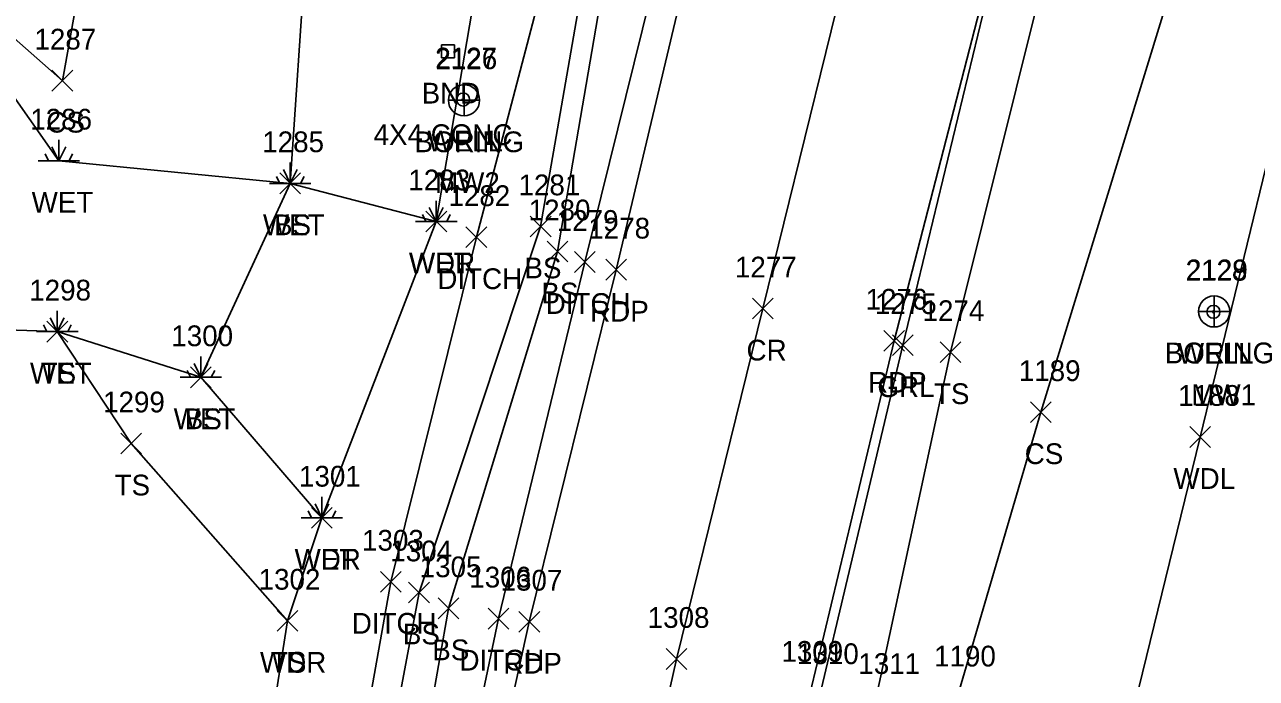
# Model space of a CAD drawing. Extents: x 1551995 to 1555700, y 777276 to 783130.
# Drawn here: x 1554843.1 to 1554961.7, y 777956 to 778019 of the extents above; entities that cross this region are included whole.
import ezdxf

# ---------------------------------------------------------------- set-up
doc = ezdxf.new("R2010")
doc.units = 0
for name, color, linetype in [('D_A', 7, 'Continuous'), ('D_I', 7, 'Continuous'), ('D_TIC', 7, 'Continuous'), ('DD', 7, 'Continuous'), ('G_A', 7, 'Continuous'), ('G_I', 7, 'Continuous'), ('GA_P', 7, 'Continuous'), ('L_A', 7, 'Continuous'), ('L_I', 7, 'Continuous'), ('L_TIC', 7, 'Continuous'), ('LAWA', 7, 'Continuous'), ('LELB', 7, 'Continuous'), ('Level 18', 7, 'Continuous'), ('LWET', 7, 'Continuous'), ('M_A', 7, 'Continuous'), ('M_C', 7, 'Continuous'), ('P_A', 7, 'Continuous'), ('P_I', 7, 'Continuous'), ('P_TIC', 7, 'Continuous'), ('PET', 7, 'Continuous'), ('PRC', 7, 'Continuous'), ('R_A', 7, 'Continuous'), ('R_I', 7, 'Continuous'), ('R_TIC', 7, 'Continuous'), ('RGR', 7, 'Continuous'), ('U_A', 7, 'Continuous'), ('U_C', 7, 'Continuous'), ('U_I', 7, 'Continuous'), ('UWW', 7, 'Continuous')]:
    doc.layers.add(name, color=color, linetype=linetype)

msp = doc.modelspace()

# ---------------------------------------------------------------- linework, layer by layer
at = {"layer": 'D_TIC'}
for points in [[(1554885.57, 777997.5), (1554887.57, 777999.5)], [(1554887.57, 777997.5), (1554885.57, 777999.5)], [(1554896.01, 777995.11), (1554898.01, 777997.11)], [(1554898.01, 777995.11), (1554896.01, 777997.11)], [(1554877.33, 777964.3), (1554879.33, 777966.3)], [(1554879.33, 777964.3), (1554877.33, 777966.3)], [(1554887.71, 777960.75), (1554889.71, 777962.75)], [(1554889.71, 777960.75), (1554887.71, 777962.75)]]:
    msp.add_lwpolyline(points, dxfattribs=at)
at = {"layer": 'DD'}
for points in [[(1554922.06, 778109.96), (1554923.19, 778109.15), (1554925.69, 778108.05), (1554928.67, 778106.77), (1554922.03, 778089.94), (1554922.01, 778087.44), (1554918.96, 778075.67), (1554907.32, 778037.79), (1554897.01, 777996.11), (1554888.71, 777961.75), (1554879.52, 777917.82), (1554870.92, 777875.83), (1554859.53, 777827.03), (1554848.28, 777775.3), (1554842.42, 777742.65), (1554832.08, 777696.16), (1554826.68, 777674.46), (1554825.9, 777662.94)], [(1554922.06, 778109.96), (1554914.41, 778091.96), (1554910.4, 778079.82), (1554897.71, 778040.99), (1554886.57, 777998.5), (1554878.33, 777965.3), (1554870.22, 777919.72), (1554862.18, 777878.39), (1554853.39, 777826.98), (1554841.81, 777777.5)]]:
    msp.add_lwpolyline(points, dxfattribs=at)
at = {"layer": 'GA_P'}
for p, q in [((1554885.38, 778011.69), (1554885.38, 778013.19)), ((1554885.38, 778011.69), (1554883.88, 778011.69)), ((1554886.88, 778011.69), (1554885.38, 778011.69)), ((1554885.38, 778010.19), (1554885.38, 778011.69)), ((1554957.62, 777991.35), (1554957.62, 777992.85)), ((1554957.62, 777991.35), (1554956.12, 777991.35)), ((1554959.12, 777991.35), (1554957.62, 777991.35)), ((1554957.62, 777989.85), (1554957.62, 777991.35))]:
    msp.add_line(p, q, dxfattribs=at)
for centre, start, end in [((1554885.38, 778011.69), 90, 180), ((1554885.38, 778011.69), 0, 90), ((1554885.38, 778011.69), 180, 270), ((1554885.38, 778011.69), 270, 0), ((1554957.62, 777991.35), 90, 180), ((1554957.62, 777991.35), 0, 90), ((1554957.62, 777991.35), 180, 270), ((1554957.62, 777991.35), 270, 0)]:
    msp.add_arc(centre, 1.5, start, end, dxfattribs=at)
at = {"layer": 'L_TIC'}
for points in [[(1554845.7, 778012.58), (1554847.7, 778014.58)], [(1554847.7, 778012.58), (1554845.7, 778014.58)], [(1554867.64, 778002.69), (1554869.64, 778004.69)], [(1554869.64, 778002.69), (1554867.64, 778004.69)], [(1554881.71, 777999.01), (1554883.71, 778001.01)], [(1554883.71, 777999.01), (1554881.71, 778001.01)], [(1554891.76, 777998.54), (1554893.76, 778000.54)], [(1554893.76, 777998.54), (1554891.76, 778000.54)], [(1554893.39, 777996.12), (1554895.39, 777998.12)], [(1554895.39, 777996.12), (1554893.39, 777998.12)], [(1554845.21, 777988.4), (1554847.21, 777990.4)], [(1554847.21, 777988.4), (1554845.21, 777990.4)], [(1554931.23, 777986.42), (1554933.23, 777988.42)], [(1554933.23, 777986.42), (1554931.23, 777988.42)], [(1554859.04, 777984), (1554861.04, 777986)], [(1554861.04, 777984), (1554859.04, 777986)], [(1554939.94, 777980.64), (1554941.94, 777982.64)], [(1554941.94, 777980.64), (1554939.94, 777982.64)], [(1554955.28, 777978.25), (1554957.28, 777980.25)], [(1554957.28, 777978.25), (1554955.28, 777980.25)], [(1554852.32, 777977.62), (1554854.32, 777979.62)], [(1554854.32, 777977.62), (1554852.32, 777979.62)], [(1554870.69, 777970.47), (1554872.69, 777972.47)], [(1554872.69, 777970.47), (1554870.69, 777972.47)], [(1554880.05, 777963.27), (1554882.05, 777965.27)], [(1554882.05, 777963.27), (1554880.05, 777965.27)], [(1554882.88, 777961.74), (1554884.88, 777963.74)], [(1554884.88, 777961.74), (1554882.88, 777963.74)], [(1554867.37, 777960.54), (1554869.37, 777962.54)], [(1554869.37, 777960.54), (1554867.37, 777962.54)], [(1554867.37, 777960.54), (1554869.37, 777962.54)], [(1554869.37, 777960.54), (1554867.37, 777962.54)]]:
    msp.add_lwpolyline(points, dxfattribs=at)
at = {"layer": 'LAWA'}
for points in [[(1555000.96, 778294.87), (1554977.33, 778249.83), (1554953.65, 778203.43), (1554934.13, 778158.37), (1554921.74, 778129.69), (1554915, 778109.12), (1554905.48, 778082.18), (1554899.62, 778064.01), (1554889.87, 778042.09), (1554882.71, 778000.01), (1554871.69, 777971.47), (1554868.37, 777961.54), (1554861.96, 777920.45), (1554858.53, 777878.75), (1554855.37, 777850.35), (1554848.67, 777827.4), (1554836.72, 777779.63)], [(1555085.12, 778246.6), (1555062.11, 778217.51), (1555036.75, 778197.89), (1555030.02, 778178.79), (1555023.09, 778154.13), (1555005.22, 778133.85), (1555000.72, 778121.06), (1554983.85, 778091.44), (1554975.19, 778092.03), (1554970.99, 778074.93), (1554967.22, 778059.88), (1554967.17, 778023.98), (1554956.28, 777979.25), (1554949.24, 777950.5), (1554942.15, 777917.97), (1554937.88, 777884.35), (1554924.17, 777845.95), (1554911.99, 777797.39)]]:
    msp.add_lwpolyline(points, dxfattribs=at)
at = {"layer": 'LELB'}
for points in [[(1555012.41, 778287.51), (1554987.42, 778242.35), (1554964.94, 778198.34), (1554949.46, 778165.73), (1554942.04, 778145.43), (1554936.48, 778136), (1554931.2, 778126.36), (1554925.41, 778115.96), (1554925.69, 778108.05), (1554919.03, 778090.31), (1554918.44, 778089.95), (1554914.24, 778077.2), (1554901.57, 778039.07), (1554894.39, 777997.12), (1554883.88, 777962.74), (1554876.08, 777918.21), (1554866.8, 777876.47), (1554857.76, 777827.38), (1554846.36, 777775.83)], [(1554925.41, 778115.96), (1554923.19, 778109.15), (1554916.16, 778091.42), (1554916.06, 778090.22), (1554912.35, 778078.2), (1554899.83, 778040.36), (1554892.76, 777999.54), (1554881.05, 777964.27), (1554872.66, 777919.49), (1554864.33, 777877.23), (1554855.73, 777827.33), (1554843.83, 777776.52)], [(1554891.95, 778090.96), (1554875.6, 778057.42), (1554871.64, 778048.29), (1554868.64, 778003.69), (1554860.04, 777985)], [(1554956.78, 778082.85), (1554952.54, 778067.25), (1554941.7, 778025.45), (1554932.23, 777987.42), (1554924.92, 777953.42), (1554914.28, 777909.64), (1554906.04, 777867.54), (1554895.88, 777821.34), (1554882.23, 777767.05), (1554874.85, 777730.37), (1554865.16, 777689.06), (1554854.06, 777643.96), (1554841.07, 777598.56), (1554825.8, 777560.58)], [(1554828.48, 778068.89), (1554831.99, 778058.27), (1554852.66, 778046.95), (1554846.7, 778013.58), (1554831.58, 778026.93)], [(1554954.84, 778026.93), (1554940.94, 777981.64), (1554932.87, 777954.14), (1554929.76, 777924.84), (1554918.75, 777893.91), (1554912.39, 777848.48), (1554900.26, 777799.7), (1554891.71, 777757.62), (1554881.43, 777720.27), (1554874.58, 777680.06), (1554873.83, 777672.65), (1554864.12, 777644.24), (1554854.56, 777607.14), (1554832.26, 777556.58)], [(1554846.21, 777989.4), (1554853.32, 777978.62), (1554868.37, 777961.54)]]:
    msp.add_lwpolyline(points, dxfattribs=at)
at = {"layer": 'Level 18'}
for p, q in [((1554884.46, 778017.04), (1554883.21, 778017.04)), ((1554883.21, 778017.04), (1554883.21, 778015.79)), ((1554884.46, 778017.04), (1554883.21, 778017.04)), ((1554883.21, 778017.04), (1554883.21, 778015.79)), ((1554884.46, 778015.79), (1554884.46, 778017.04)), ((1554884.46, 778015.79), (1554884.46, 778017.04)), ((1554883.21, 778015.79), (1554884.46, 778015.79)), ((1554883.21, 778015.79), (1554884.46, 778015.79))]:
    msp.add_line(p, q, dxfattribs=at)
msp.add_circle((1554883.81, 778016.38), 0.0833, dxfattribs=at)
at = {"layer": 'LWET'}
for p, q in [((1554846.36, 778005.87), (1554845.69, 778007.2)), ((1554846.36, 778005.87), (1554846.36, 778007.87)), ((1554846.36, 778005.87), (1554847.03, 778007.2)), ((1554848.36, 778005.87), (1554844.36, 778005.87)), ((1554845.36, 778005.87), (1554845.03, 778006.53)), ((1554847.36, 778005.87), (1554847.69, 778006.53)), ((1554868.64, 778003.69), (1554867.98, 778005.02)), ((1554868.64, 778003.69), (1554868.64, 778005.69)), ((1554868.64, 778003.69), (1554869.31, 778005.02)), ((1554870.64, 778003.69), (1554866.64, 778003.69)), ((1554867.64, 778003.69), (1554867.31, 778004.35)), ((1554869.64, 778003.69), (1554869.98, 778004.35)), ((1554882.71, 778000.01), (1554882.04, 778001.35)), ((1554882.71, 778000.01), (1554882.71, 778002.01)), ((1554882.71, 778000.01), (1554883.38, 778001.35)), ((1554884.71, 778000.01), (1554880.71, 778000.01)), ((1554881.71, 778000.01), (1554881.38, 778000.68)), ((1554883.71, 778000.01), (1554884.04, 778000.68)), ((1554846.21, 777989.4), (1554845.54, 777990.73)), ((1554846.21, 777989.4), (1554846.21, 777991.4)), ((1554846.21, 777989.4), (1554846.87, 777990.73)), ((1554848.21, 777989.4), (1554844.21, 777989.4)), ((1554845.21, 777989.4), (1554844.87, 777990.07)), ((1554847.21, 777989.4), (1554847.54, 777990.07)), ((1554860.04, 777985), (1554860.04, 777987)), ((1554859.04, 777985), (1554858.71, 777985.67)), ((1554860.04, 777985), (1554859.38, 777986.33)), ((1554860.04, 777985), (1554860.71, 777986.33)), ((1554861.04, 777985), (1554861.38, 777985.67)), ((1554862.04, 777985), (1554858.04, 777985)), ((1554871.69, 777971.47), (1554871.03, 777972.8)), ((1554871.69, 777971.47), (1554871.69, 777973.47)), ((1554871.69, 777971.47), (1554872.36, 777972.8)), ((1554873.69, 777971.47), (1554869.69, 777971.47)), ((1554870.69, 777971.47), (1554870.36, 777972.13)), ((1554872.69, 777971.47), (1554873.03, 777972.13))]:
    msp.add_line(p, q, dxfattribs=at)
msp.add_lwpolyline([(1554882.71, 778000.01), (1554868.64, 778003.69), (1554846.36, 778005.87), (1554831.58, 778026.93), (1554823.16, 778037.44), (1554819.96, 778020.55), (1554830.86, 778003.24), (1554813.29, 778001.4), (1554818.74, 777989.99), (1554828.62, 777989.99), (1554846.21, 777989.4), (1554860.04, 777985), (1554871.69, 777971.47)], dxfattribs=at)
at = {"layer": 'P_TIC'}
for points in [[(1554899.04, 777994.37), (1554901.04, 777996.37)], [(1554901.04, 777994.37), (1554899.04, 777996.37)], [(1554913.16, 777990.62), (1554915.16, 777992.62)], [(1554915.16, 777990.62), (1554913.16, 777992.62)], [(1554925.8, 777987.52), (1554927.8, 777989.52)], [(1554927.8, 777987.52), (1554925.8, 777989.52)], [(1554890.67, 777960.45), (1554892.67, 777962.45)], [(1554892.67, 777960.45), (1554890.67, 777962.45)], [(1554904.84, 777956.86), (1554906.84, 777958.86)], [(1554906.84, 777956.86), (1554904.84, 777958.86)]]:
    msp.add_lwpolyline(points, dxfattribs=at)
at = {"layer": 'PET'}
for points in [[(1555086.85, 778385.99), (1555058.53, 778347.95), (1555034.13, 778312.76), (1555016.69, 778284.76), (1554990.68, 778240.38), (1554968.05, 778196.33), (1554953.03, 778164.25), (1554940.37, 778132.83), (1554930.99, 778106.02), (1554923.77, 778083.63), (1554909.85, 778036.75), (1554900.04, 777995.37), (1554891.67, 777961.45), (1554881.9, 777917.03), (1554872.92, 777875.28), (1554862.74, 777826.66), (1554851.19, 777774.32)], [(1555108.52, 778369.81), (1555078.86, 778330.23), (1555056.92, 778298.28), (1555038.33, 778268.72), (1555013, 778223.52), (1554996, 778190.4), (1554978.91, 778154.53), (1554967.24, 778125.11), (1554957.25, 778096.67), (1554950.17, 778073.38), (1554937.06, 778028.22), (1554926.8, 777988.52), (1554918.72, 777954.59), (1554908.46, 777910.08), (1554899.75, 777869.14), (1554889.9, 777822.39), (1554877.4, 777767.74)]]:
    msp.add_lwpolyline(points, dxfattribs=at)
at = {"layer": 'PRC'}
msp.add_lwpolyline([(1555098.33, 778377.48), (1555069.71, 778339.49), (1555045.49, 778304.7), (1555028.73, 778278.05), (1555002.89, 778234.08), (1554980, 778189.5), (1554966.22, 778159.18), (1554954.38, 778129.46), (1554944.07, 778101.03), (1554941.59, 778092.54), (1554937.34, 778078.77), (1554924.27, 778032.77), (1554914.16, 777991.62), (1554905.84, 777957.86), (1554895.98, 777913.96), (1554886.88, 777872.59), (1554876.72, 777824.26), (1554864.6, 777770.35)], dxfattribs=at)
at = {"layer": 'R_TIC'}
for points in [[(1554926.65, 777987.1), (1554928.65, 777989.1)], [(1554928.65, 777987.1), (1554926.65, 777989.1)]]:
    msp.add_lwpolyline(points, dxfattribs=at)
at = {"layer": 'RGR'}
msp.add_lwpolyline([(1555039.56, 778268.3), (1555013.62, 778223), (1554996.63, 778189.88), (1554979.88, 778154.08), (1554968.24, 778124.65), (1554958.2, 778096.32), (1554950.97, 778072.94), (1554937.27, 778027.95), (1554927.65, 777988.1), (1554919.66, 777954.37), (1554909.72, 777910.11), (1554900.5, 777868.18), (1554890.69, 777822.54), (1554878.36, 777767.59), (1554870.52, 777731.32), (1554860.9, 777689.38), (1554849.55, 777645.14), (1554835.81, 777600.33), (1554822.79, 777564.15), (1554817.07, 777548.72), (1554816.7, 777536.06)], dxfattribs=at)
at = {"layer": 'UWW'}
for centre, radius in [((1554885.3, 778011.76), 0.625), ((1554885.3, 778011.76), 0.0833), ((1554957.56, 777991.31), 0.625), ((1554957.56, 777991.31), 0.0833)]:
    msp.add_circle(centre, radius, dxfattribs=at)

# ---------------------------------------------------------------- texts
at = {"layer": 'D_A'}
for p in [(1554882.81, 777993.5), (1554893.25, 777991.11), (1554874.57, 777960.3), (1554884.95, 777956.75)]:
    msp.add_text('DITCH', height=2, dxfattribs=at).set_placement(p)
at = {"layer": 'D_I'}
for s, p in [('1282', (1554883.88, 778001.5)), ('1279', (1554894.31, 777999.11)), ('1303', (1554875.56, 777968.3)), ('1306', (1554885.89, 777964.75))]:
    msp.add_text(s, height=2, dxfattribs=at).set_placement(p)
at = {"layer": 'G_A'}
for p in [(1554880.61, 778006.69), (1554952.86, 777986.35)]:
    msp.add_text('BORING', height=2, dxfattribs=at).set_placement(p)
at = {"layer": 'G_I'}
for s, p in [('2126', (1554882.63, 778014.69)), ('2129', (1554954.92, 777994.35))]:
    msp.add_text(s, height=2, dxfattribs=at).set_placement(p)
at = {"layer": 'L_A'}
for s, p in [('CS', (1554845.15, 778008.58)), ('WET', (1554843.74, 778000.87)), ('WET', (1554866.02, 777998.69)), ('BS', (1554867.08, 777998.69)), ('WDR', (1554880.07, 777995.01)), ('WET', (1554880.09, 777995.01)), ('BS', (1554891.2, 777994.54)), ('BS', (1554892.83, 777992.12)), ('WET', (1554843.58, 777984.4)), ('TS', (1554844.61, 777984.4)), ('TS', (1554930.64, 777982.42)), ('WET', (1554857.42, 777980)), ('BS', (1554858.49, 777980)), ('CS', (1554939.38, 777976.64)), ('WDL', (1554953.7, 777974.25)), ('TS', (1554851.73, 777973.62)), ('WDR', (1554869.06, 777966.47)), ('WET', (1554869.07, 777966.47)), ('BS', (1554879.49, 777959.27)), ('BS', (1554882.32, 777957.74)), ('WDR', (1554865.73, 777956.54)), ('TS', (1554866.78, 777956.54))]:
    msp.add_text(s, height=2, dxfattribs=at).set_placement(p)
at = {"layer": 'L_I'}
for s, p in [('1287', (1554844.01, 778016.58)), ('1286', (1554843.61, 778008.87)), ('1285', (1554865.95, 778006.69)), ('1285', (1554865.95, 778006.69)), ('1283', (1554880.02, 778003.01)), ('1283', (1554880.02, 778003.01)), ('1281', (1554890.63, 778002.54)), ('1280', (1554891.61, 778000.12)), ('1298', (1554843.51, 777992.4)), ('1298', (1554843.51, 777992.4)), ('1274', (1554929.54, 777990.42)), ('1300', (1554857.19, 777988)), ('1300', (1554857.19, 777988)), ('1189', (1554938.81, 777984.64)), ('1299', (1554850.62, 777981.62)), ('1188', (1554954.15, 777982.25)), ('1301', (1554869.49, 777974.47)), ('1301', (1554869.49, 777974.47)), ('1304', (1554878.28, 777967.27)), ('1305', (1554881.11, 777965.74)), ('1302', (1554865.6, 777964.54)), ('1302', (1554865.6, 777964.54)), ('1311', (1554923.36, 777956.42)), ('1190', (1554930.65, 777957.14))]:
    msp.add_text(s, height=2, dxfattribs=at).set_placement(p)
at = {"layer": 'M_A'}
msp.add_text('BND', height=2, dxfattribs=at).set_placement((1554881.3, 778011.38))
at = {"layer": 'M_C'}
msp.add_text('4X4 CONC', height=2, dxfattribs=at).set_placement((1554876.67, 778007.38))
at = {"layer": 'P_A'}
for s, p in [('RDP', (1554897.53, 777990.37)), ('CR', (1554912.59, 777986.62)), ('RDP', (1554924.29, 777983.52)), ('RDP', (1554889.16, 777956.45))]:
    msp.add_text(s, height=2, dxfattribs=at).set_placement(p)
at = {"layer": 'P_I'}
for s, p in [('1278', (1554897.35, 777998.37)), ('1277', (1554911.47, 777994.62)), ('1276', (1554924.05, 777991.52)), ('1307', (1554888.9, 777964.45)), ('1308', (1554903.07, 777960.86)), ('1309', (1554915.95, 777957.59))]:
    msp.add_text(s, height=2, dxfattribs=at).set_placement(p)
at = {"layer": 'R_A'}
msp.add_text('GRL', height=2, dxfattribs=at).set_placement((1554925.19, 777983.1))
at = {"layer": 'R_I'}
for s, p in [('1275', (1554924.95, 777991.1)), ('1310', (1554917.45, 777957.37))]:
    msp.add_text(s, height=2, dxfattribs=at).set_placement(p)
at = {"layer": 'U_A'}
for p in [(1554881.86, 778006.76), (1554954.13, 777986.31)]:
    msp.add_text('WELL', height=2, dxfattribs=at).set_placement(p)
at = {"layer": 'U_C'}
for s, p in [('MW2', (1554882.59, 778002.76)), ('MW1', (1554955.42, 777982.31))]:
    msp.add_text(s, height=2, dxfattribs=at).set_placement(p)
at = {"layer": 'U_I'}
for s, p in [('2127', (1554882.6, 778014.76)), ('2128', (1554954.87, 777994.31))]:
    msp.add_text(s, height=2, dxfattribs=at).set_placement(p)

doc.saveas('drawing.dxf')
